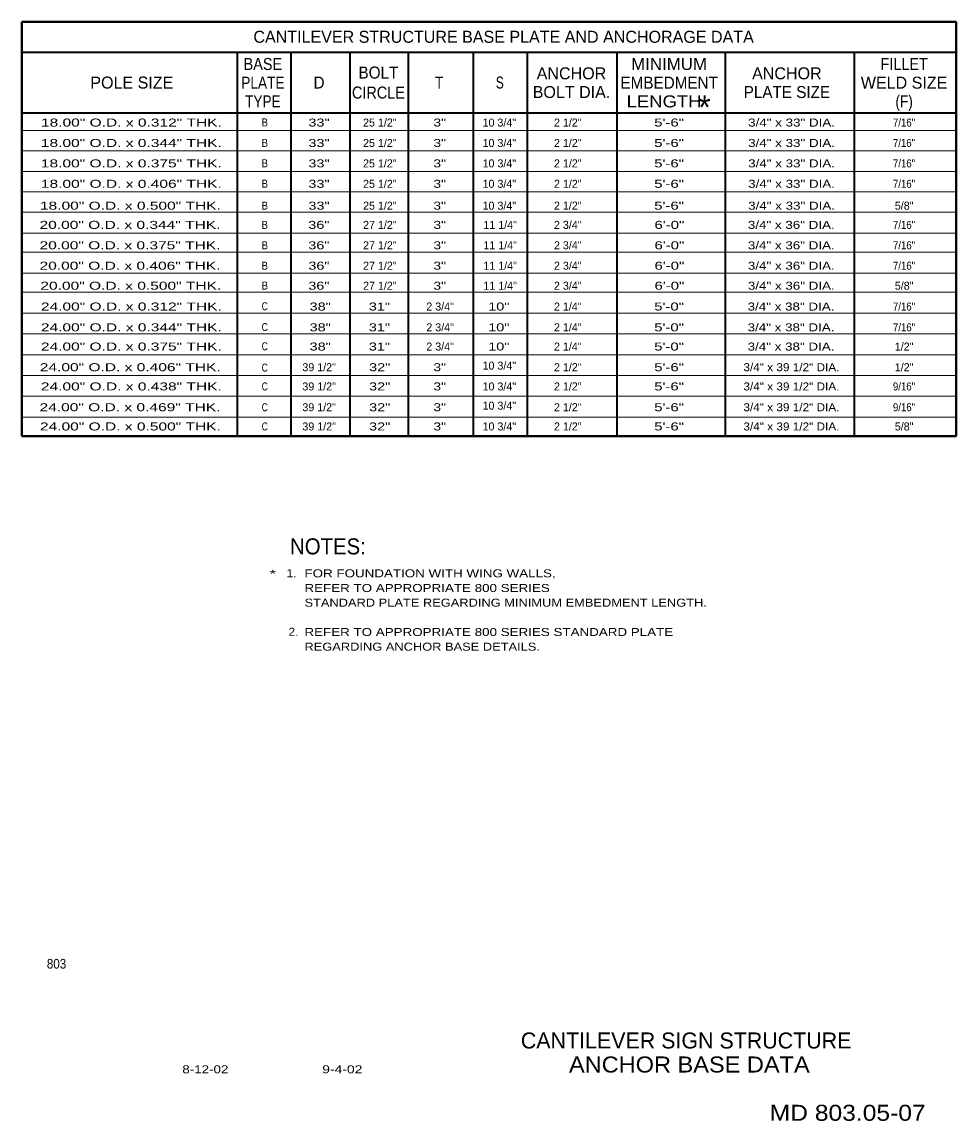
# Model space of a CAD drawing. Extents: x -34845.44 to -34838.43, y -181513.92 to -181505.68.
import ezdxf
from ezdxf.enums import TextEntityAlignment as Align

# ---------------------------------------------------------------- set-up
doc = ezdxf.new("R2010")
doc.units = 0
doc.header["$LTSCALE"] = 0.024
doc.layers.add('1', color=7, linetype='Continuous', lineweight=13)
doc.layers.add('12', color=7, linetype='Continuous')
doc.layers.add('13', color=7, linetype='Continuous')

msp = doc.modelspace()

# ---------------------------------------------------------------- linework, layer by layer
at = {"layer": '1', "lineweight": 40}
for p, q in [((-34838.433, -181505.678), (-34845.436, -181505.678)), ((-34845.436, -181505.678), (-34845.436, -181508.784)), ((-34838.433, -181508.784), (-34838.433, -181505.678)), ((-34838.433, -181508.784), (-34845.436, -181508.784))]:
    msp.add_line(p, q, dxfattribs=at)
at = {"layer": '1', "lineweight": 35}
for p, q in [((-34838.433, -181505.906), (-34845.436, -181505.906)), ((-34843.822, -181505.906), (-34843.822, -181508.784)), ((-34843.42, -181505.906), (-34843.42, -181508.784)), ((-34842.978, -181505.906), (-34842.978, -181508.784)), ((-34842.54, -181505.906), (-34842.54, -181508.784)), ((-34842.052, -181505.906), (-34842.052, -181508.784)), ((-34841.649, -181505.906), (-34841.649, -181508.784)), ((-34840.976, -181505.906), (-34840.976, -181508.784)), ((-34840.165, -181505.906), (-34840.165, -181508.784)), ((-34839.196, -181505.906), (-34839.196, -181508.784)), ((-34838.433, -181506.361), (-34845.436, -181506.361))]:
    msp.add_line(p, q, dxfattribs=at)
at = {"layer": '1'}
for p, q in [((-34838.433, -181506.492), (-34845.436, -181506.492)), ((-34838.433, -181506.645), (-34845.436, -181506.645)), ((-34838.433, -181506.798), (-34845.436, -181506.798)), ((-34838.433, -181506.951), (-34845.436, -181506.951)), ((-34838.433, -181507.104), (-34845.436, -181507.104)), ((-34838.433, -181507.26), (-34845.436, -181507.26)), ((-34838.433, -181507.404), (-34845.436, -181507.404)), ((-34838.433, -181507.56), (-34845.436, -181507.56)), ((-34838.433, -181507.704), (-34845.436, -181507.704)), ((-34838.433, -181507.86), (-34845.436, -181507.86)), ((-34838.433, -181508.016), (-34845.436, -181508.016)), ((-34838.433, -181508.172), (-34845.436, -181508.172)), ((-34838.433, -181508.328), (-34845.436, -181508.328)), ((-34838.433, -181508.484), (-34845.436, -181508.484)), ((-34838.433, -181508.64), (-34845.436, -181508.64))]:
    msp.add_line(p, q, dxfattribs=at)

# ---------------------------------------------------------------- texts
at = {"layer": '12'}
for s, height, p in [('CANTILEVER STRUCTURE BASE PLATE AND ANCHORAGE DATA', 0.09, (-34841.825, -181505.834)), ('ANCHOR', 0.09, (-34841.316, -181506.108)), ('ANCHOR', 0.09, (-34839.701, -181506.108)), ('POLE SIZE', 0.09, (-34844.6125, -181506.177)), ('WELD SIZE', 0.09, (-34838.8225, -181506.178)), ('BOLT DIA.', 0.09, (-34841.316, -181506.248)), ('*', 0.18, (-34840.3185, -181506.407))]:
    msp.add_text(s, height=height, dxfattribs=at).set_placement(p, align=Align.CENTER)
for s, width, p in [('BASE', 0.9, (-34843.63, -181506.038)), ('MINIMUM', 1.05, (-34840.5845, -181506.038)), ('FILLET', 0.9, (-34838.8215, -181506.038)), ('BOLT', 0.95, (-34842.7635, -181506.102)), ('PLATE', 0.85, (-34843.6295, -181506.178)), ('D', 0.95, (-34843.2085, -181506.177)), ('T', 0.85, (-34842.308, -181506.177)), ('S', 0.75, (-34841.8535, -181506.177)), ('EMBEDMENT', 0.95, (-34840.5835, -181506.178)), ('CIRCLE', 0.9, (-34842.7635, -181506.252)), ('PLATE SIZE', 0.95, (-34839.701, -181506.248)), ('TYPE', 0.85, (-34843.63, -181506.318)), ('LENGTH  ', 1.15, (-34840.5835, -181506.318)), ('(F)', 0.85, (-34838.822, -181506.318))]:
    msp.add_text(s, height=0.09, dxfattribs=dict(at, width=width)).set_placement(p, align=Align.CENTER)
at = {"layer": '13'}
for s, height, width, p in [('18.00" O.D. x 0.312" THK.', 0.06, 1.45, (-34844.6155, -181506.462)), ('B', 0.06, 0.9, (-34843.6155, -181506.461)), ('33"', 0.06, 1.35, (-34843.209, -181506.462)), ('3"', 0.06, 1.3, (-34842.304, -181506.462)), ('5\'-6"', 0.06, 1.4, (-34840.584, -181506.462)), ('3/4" x 33" DIA.', 0.06, 1.25, (-34839.666, -181506.462)), ('7/16"', 0.06, 0.9, (-34838.823, -181506.462)), ('18.00" O.D. x 0.344" THK.', 0.06, 1.45, (-34844.616, -181506.615)), ('B', 0.06, 0.9, (-34843.6155, -181506.614)), ('33"', 0.06, 1.35, (-34843.209, -181506.615)), ('3"', 0.06, 1.3, (-34842.304, -181506.615)), ('5\'-6"', 0.06, 1.4, (-34840.584, -181506.615)), ('3/4" x 33" DIA.', 0.06, 1.25, (-34839.666, -181506.615)), ('7/16"', 0.06, 0.9, (-34838.823, -181506.615)), ('18.00" O.D. x 0.375" THK.', 0.06, 1.45, (-34844.616, -181506.768)), ('B', 0.06, 0.9, (-34843.6155, -181506.767)), ('33"', 0.06, 1.35, (-34843.209, -181506.768)), ('3"', 0.06, 1.3, (-34842.304, -181506.768)), ('5\'-6"', 0.06, 1.4, (-34840.584, -181506.768)), ('3/4" x 33" DIA.', 0.06, 1.25, (-34839.666, -181506.768)), ('7/16"', 0.06, 0.9, (-34838.823, -181506.768)), ('18.00" O.D. x 0.406" THK.', 0.06, 1.45, (-34844.616, -181506.921)), ('B', 0.06, 0.9, (-34843.6155, -181506.92)), ('33"', 0.06, 1.35, (-34843.209, -181506.921)), ('3"', 0.06, 1.3, (-34842.304, -181506.921)), ('5\'-6"', 0.06, 1.4, (-34840.584, -181506.921)), ('3/4" x 33" DIA.', 0.06, 1.25, (-34839.666, -181506.921)), ('7/16"', 0.06, 0.9, (-34838.823, -181506.921)), ('18.00" O.D. x 0.500" THK.', 0.06, 1.45, (-34844.623, -181507.085)), ('B', 0.06, 0.9, (-34843.6155, -181507.085)), ('33"', 0.06, 1.35, (-34843.209, -181507.085)), ('3"', 0.06, 1.3, (-34842.304, -181507.085)), ('5\'-6"', 0.06, 1.4, (-34840.584, -181507.085)), ('3/4" x 33" DIA.', 0.06, 1.25, (-34839.666, -181507.085)), ('20.00" O.D. x 0.344" THK.', 0.06, 1.45, (-34844.626, -181507.229)), ('B', 0.06, 0.9, (-34843.6155, -181507.229)), ('36"', 0.06, 1.35, (-34843.21, -181507.229)), ('3"', 0.06, 1.3, (-34842.304, -181507.229)), ('6\'-0"', 0.06, 1.4, (-34840.582, -181507.229)), ('3/4" x 36" DIA.', 0.06, 1.25, (-34839.668, -181507.229)), ('7/16"', 0.06, 0.9, (-34838.823, -181507.229)), ('20.00" O.D. x 0.375" THK.', 0.06, 1.45, (-34844.626, -181507.382)), ('B', 0.06, 0.9, (-34843.6155, -181507.382)), ('36"', 0.06, 1.35, (-34843.21, -181507.382)), ('3"', 0.06, 1.3, (-34842.304, -181507.382)), ('6\'-0"', 0.06, 1.4, (-34840.582, -181507.382)), ('3/4" x 36" DIA.', 0.06, 1.25, (-34839.668, -181507.382)), ('7/16"', 0.06, 0.9, (-34838.823, -181507.382)), ('20.00" O.D. x 0.406" THK.', 0.06, 1.45, (-34844.626, -181507.535)), ('B', 0.06, 0.9, (-34843.6155, -181507.535)), ('36"', 0.06, 1.35, (-34843.21, -181507.535)), ('3"', 0.06, 1.3, (-34842.304, -181507.535)), ('6\'-0"', 0.06, 1.4, (-34840.582, -181507.535)), ('3/4" x 36" DIA.', 0.06, 1.25, (-34839.668, -181507.535)), ('7/16"', 0.06, 0.9, (-34838.823, -181507.535)), ('20.00" O.D. x 0.500" THK.', 0.06, 1.45, (-34844.62, -181507.685)), ('B', 0.06, 0.9, (-34843.6155, -181507.684)), ('36"', 0.06, 1.35, (-34843.21, -181507.685)), ('3"', 0.06, 1.3, (-34842.304, -181507.685)), ('6\'-0"', 0.06, 1.4, (-34840.582, -181507.685)), ('3/4" x 36" DIA.', 0.06, 1.25, (-34839.668, -181507.685)), ('C', 0.06, 0.8, (-34843.6155, -181507.839)), ('3/4" x 38" DIA.', 0.06, 1.25, (-34839.67, -181507.841)), ('7/16"', 0.06, 0.9, (-34838.823, -181507.841)), ('24.00" O.D. x 0.312" THK.', 0.06, 1.45, (-34844.616, -181507.841)), ('38"', 0.06, 1.35, (-34843.2, -181507.841)), ('31"', 0.06, 1.35, (-34842.756, -181507.841)), ('10"', 0.06, 1.35, (-34841.861, -181507.841)), ('5\'-0"', 0.06, 1.4, (-34840.584, -181507.841)), ('24.00" O.D. x 0.344" THK.', 0.06, 1.45, (-34844.616, -181507.997)), ('C', 0.06, 0.8, (-34843.6155, -181507.995)), ('38"', 0.06, 1.35, (-34843.2, -181507.997)), ('31"', 0.06, 1.35, (-34842.756, -181507.997)), ('10"', 0.06, 1.35, (-34841.861, -181507.997)), ('5\'-0"', 0.06, 1.4, (-34840.584, -181507.997)), ('3/4" x 38" DIA.', 0.06, 1.25, (-34839.67, -181507.997)), ('7/16"', 0.06, 0.9, (-34838.823, -181507.997)), ('24.00" O.D. x 0.375" THK.', 0.06, 1.45, (-34844.616, -181508.141)), ('C', 0.06, 0.8, (-34843.6155, -181508.139)), ('38"', 0.06, 1.35, (-34843.2, -181508.141)), ('31"', 0.06, 1.35, (-34842.756, -181508.141)), ('10"', 0.06, 1.35, (-34841.861, -181508.141)), ('5\'-0"', 0.06, 1.4, (-34840.584, -181508.141)), ('3/4" x 38" DIA.', 0.06, 1.25, (-34839.67, -181508.141)), ('24.00" O.D. x 0.406" THK.', 0.06, 1.45, (-34844.624, -181508.296)), ('C', 0.06, 0.8, (-34843.6155, -181508.299)), ('32"', 0.06, 1.35, (-34842.754, -181508.296)), ('3"', 0.06, 1.3, (-34842.304, -181508.296)), ('5\'-6"', 0.06, 1.4, (-34840.584, -181508.296)), ('3/4" x 39 1/2" DIA.', 0.06, 1.1, (-34839.667, -181508.296)), ('24.00" O.D. x 0.438" THK.', 0.06, 1.45, (-34844.616, -181508.44)), ('C', 0.06, 0.8, (-34843.6155, -181508.44)), ('32"', 0.06, 1.35, (-34842.754, -181508.44)), ('3"', 0.06, 1.3, (-34842.304, -181508.44)), ('5\'-6"', 0.06, 1.4, (-34840.584, -181508.44)), ('3/4" x 39 1/2" DIA.', 0.06, 1.1, (-34839.667, -181508.44)), ('9/16"', 0.06, 0.9, (-34838.823, -181508.44)), ('24.00" O.D. x 0.469" THK.', 0.06, 1.45, (-34844.626, -181508.596)), ('C', 0.06, 0.8, (-34843.6155, -181508.596)), ('32"', 0.06, 1.35, (-34842.754, -181508.596)), ('3"', 0.06, 1.3, (-34842.304, -181508.596)), ('5\'-6"', 0.06, 1.4, (-34840.584, -181508.596)), ('3/4" x 39 1/2" DIA.', 0.06, 1.1, (-34839.667, -181508.596)), ('9/16"', 0.06, 0.9, (-34838.823, -181508.596)), ('24.00" O.D. x 0.500" THK.', 0.06, 1.45, (-34844.623, -181508.74)), ('C', 0.06, 0.8, (-34843.6155, -181508.74)), ('32"', 0.06, 1.35, (-34842.754, -181508.74)), ('3"', 0.06, 1.3, (-34842.304, -181508.74)), ('5\'-6"', 0.06, 1.4, (-34840.584, -181508.74)), ('3/4" x 39 1/2" DIA.', 0.06, 1.1, (-34839.667, -181508.74)), ('NOTES:', 0.12, 0.95, (-34843.142, -181509.669)), ('803', 0.07251, 0.9, (-34845.177, -181512.774)), (' ANCHOR BASE DATA', 0.12, 1.1, (-34840.457, -181513.553))]:
    msp.add_text(s, height=height, dxfattribs=dict(at, width=width)).set_placement(p, align=Align.CENTER)
for s, height, p in [('25 1/2"', 0.06, (-34842.753, -181506.462)), ('10 3/4"', 0.06, (-34841.857, -181506.462)), ('2 1/2"', 0.06, (-34841.344, -181506.462)), ('25 1/2"', 0.06, (-34842.753, -181506.615)), ('10 3/4"', 0.06, (-34841.857, -181506.615)), ('2 1/2"', 0.06, (-34841.344, -181506.615)), ('25 1/2"', 0.06, (-34842.753, -181506.768)), ('10 3/4"', 0.06, (-34841.857, -181506.768)), ('2 1/2"', 0.06, (-34841.344, -181506.768)), ('25 1/2"', 0.06, (-34842.753, -181506.921)), ('10 3/4"', 0.06, (-34841.857, -181506.921)), ('2 1/2"', 0.06, (-34841.344, -181506.921)), ('25 1/2"', 0.06, (-34842.753, -181507.085)), ('10 3/4"', 0.06, (-34841.857, -181507.085)), ('2 1/2"', 0.06, (-34841.344, -181507.085)), ('5/8"', 0.06, (-34838.822, -181507.085)), ('27 1/2"', 0.06, (-34842.753, -181507.229)), ('11 1/4"', 0.06, (-34841.851, -181507.229)), ('2 3/4"', 0.06, (-34841.344, -181507.229)), ('27 1/2"', 0.06, (-34842.753, -181507.382)), ('11 1/4"', 0.06, (-34841.851, -181507.382)), ('2 3/4"', 0.06, (-34841.344, -181507.382)), ('27 1/2"', 0.06, (-34842.753, -181507.535)), ('11 1/4"', 0.06, (-34841.851, -181507.535)), ('2 3/4"', 0.06, (-34841.344, -181507.535)), ('27 1/2"', 0.06, (-34842.753, -181507.685)), ('11 1/4"', 0.06, (-34841.851, -181507.685)), ('2 3/4"', 0.06, (-34841.344, -181507.685)), ('5/8"', 0.06, (-34838.822, -181507.685)), ('2 3/4"', 0.06, (-34842.301, -181507.841)), ('2 1/4"', 0.06, (-34841.344, -181507.841)), ('2 3/4"', 0.06, (-34842.301, -181507.997)), ('2 1/4"', 0.06, (-34841.344, -181507.997)), ('2 3/4"', 0.06, (-34842.301, -181508.141)), ('2 1/4"', 0.06, (-34841.344, -181508.141)), ('1/2"', 0.06, (-34838.822, -181508.141)), ('39 1/2"', 0.06, (-34843.208, -181508.296)), ('10 3/4"', 0.06, (-34841.857, -181508.284)), ('2 1/2"', 0.06, (-34841.344, -181508.296)), ('1/2"', 0.06, (-34838.822, -181508.296)), ('39 1/2"', 0.06, (-34843.208, -181508.44)), ('10 3/4"', 0.06, (-34841.857, -181508.44)), ('2 1/2"', 0.06, (-34841.344, -181508.44)), ('10 3/4"', 0.06, (-34841.857, -181508.584)), ('39 1/2"', 0.06, (-34843.208, -181508.596)), ('2 1/2"', 0.06, (-34841.344, -181508.596)), ('39 1/2"', 0.06, (-34843.208, -181508.74)), ('10 3/4"', 0.06, (-34841.857, -181508.74)), ('2 1/2"', 0.06, (-34841.344, -181508.74)), ('5/8"', 0.06, (-34838.822, -181508.74)), ('CANTILEVER SIGN STRUCTURE', 0.12, (-34840.4565, -181513.373))]:
    msp.add_text(s, height=height, dxfattribs=at).set_placement(p, align=Align.CENTER)
for s, height, width, p in [('*', 0.06, 1.55, (-34843.58, -181509.844)), ('1.', 0.06, 1.1, (-34843.452, -181509.84)), ('FOR FOUNDATION WITH WING WALLS, ', 0.06, 1.25, (-34843.318, -181509.841)), ('REFER TO APPROPRIATE 800 SERIES', 0.06, 1.25, (-34843.318, -181509.951)), ('STANDARD PLATE REGARDING MINIMUM EMBEDMENT LENGTH.', 0.06, 1.2, (-34843.318, -181510.061)), ('2.', 0.06, 1.1, (-34843.437, -181510.279)), ('REFER TO APPROPRIATE 800 SERIES STANDARD PLATE', 0.06, 1.25, (-34843.318, -181510.281)), ('REGARDING ANCHOR BASE DETAILS.', 0.06, 1.2, (-34843.318, -181510.391)), ('8-12-02', 0.06, 1.25, (-34844.234, -181513.559)), ('9-4-02', 0.06, 1.3, (-34843.185, -181513.559)), ('MD 803.05-07', 0.12, 1.15, (-34839.83, -181513.915))]:
    msp.add_text(s, height=height, dxfattribs=dict(at, width=width)).set_placement(p)

doc.saveas('drawing.dxf')
